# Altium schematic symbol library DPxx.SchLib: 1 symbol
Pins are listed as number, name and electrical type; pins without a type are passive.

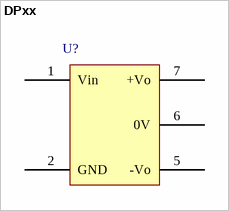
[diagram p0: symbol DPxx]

## DPxx
designator U?
footprint DPxx
pins: 1 Vin, 2 GND, 5 -Vo, 6 0V, 7 +Vo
